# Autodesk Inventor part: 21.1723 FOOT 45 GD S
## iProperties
Created: 2007-04
Part Number: 21.1723 FOOT 45 GD S
Material: Aluminum-6061
Document SubType Name: Modeling
Designer: Andy Moles
Mass: 448.401 g
Surface Area: 430.523 cm^2
Volume: 165.462 cm^3
Density: 2.71 g/cm^3
Author: Andy Moles
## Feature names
1. Base1
